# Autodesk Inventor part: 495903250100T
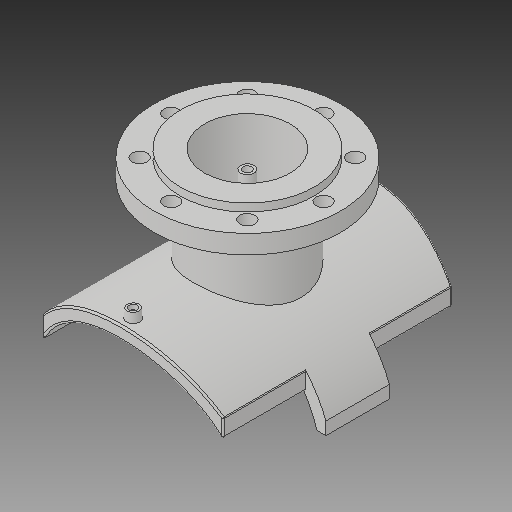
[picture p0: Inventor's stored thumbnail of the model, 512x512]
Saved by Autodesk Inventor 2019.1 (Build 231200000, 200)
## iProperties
Created: 2017-10
Part Number: 495903250100T
Material: Generic
Description: PLASSON FLANGED BRANCH SADDLE 250x100
Document SubType Name: Modeling
Designer: KIM
Mass: 2339.99 g
Surface Area: 3251.55 cm^2
Volume: 2339.99 cm^3
Density: 1 g/cm^3
Appearance: Default
Author: KIM
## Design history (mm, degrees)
derived "495904_495903.ipt"
feature "Solid1::495904_495903.ipt"
feature "Solid2::495904_495903.ipt"
tag "TaggingFeature1"
body "Solid1"
other parameters: "d1" = 15, "d2" = 213.3, "d4" = 0, "d6" = 75, "d7" = 0, "d12" = 150.6, "d13" = 14, "d14" = 135, "d16" = 5 deg, "d18" = 4, "d19" = 14, "d20" = 0, "d21" = 3, "d22" = 0, "d23" = 261, "d36" = 135, "d38" = 0, "d39" = 2, "d41" = 101, "d42" = 158, "d44" = 96.8, "d46" = 126.4, "d47" = 16, "d48" = 10.4, "d49" = 84.7, "d51" = 255, "d53" = 0, "d54" = 18, "d57" = 0, "d59" = 360 deg, "d61" = 22, "d63" = 0, "d66" = 121, "d67" = 15, "d68" = 60.5, "d70" = 0, "d71" = 2, "d72" = 237, "d_1" = 158, "B_" = 237, "H_" = 121, "x_" = 15, "D_" = 16, "DN_" = 101, "t_" = 22, "s_" = 18
